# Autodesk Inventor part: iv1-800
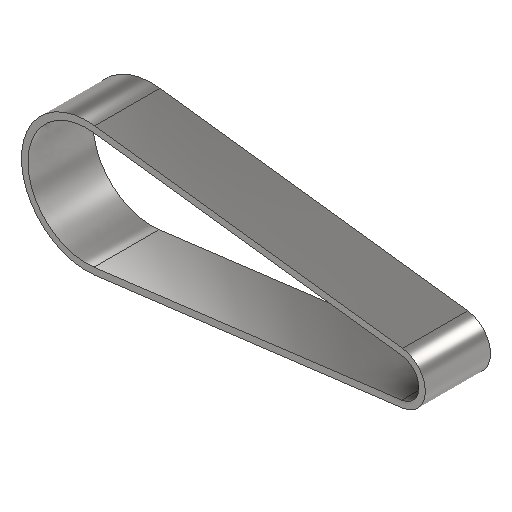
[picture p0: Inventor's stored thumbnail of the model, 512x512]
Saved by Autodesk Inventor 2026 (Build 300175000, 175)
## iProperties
Created: 2022-01
Part Number: iv1-800
Material: Steel, Mild
Document SubType Name: Modeling
Designer: Lars Bertram Pedersen
Density: 7.85 g/cm^3
Appearance: Semi-Polished
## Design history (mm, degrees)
sketch "Sketch1"
  geometry: L1 (3.125, 24.804)-(121.25, 9.922); L2 (3.125, -24.804)-(121.25, -9.922); A1 r 25 centre (0, 0) between (3.125, 24.804) and (3.125, -24.804); A2 r 10 centre (120, 0) between (121.25, -9.922) and (121.25, 9.922); 1 further point
  constraints: 4 end point, 4 point on circle, 4 tangent, 2 centre point, 1 coincident, 1 horizontal alignment
  dimensions: "d0" = 10 radius of A2; "d1" = 25 radius of A1; "d2" = 120 distance of A2.centre point (0, 0)
extrude "Extrusion1" new body sketch "Sketch1" distance "d3" = 25; taper "d4" = 0 deg
sketch "Sketch2"
  geometry: L1 (3.125, -24.804)-(121.25, -9.922) reference; L2 (121.25, 9.922)-(3.125, 24.804) reference; L3 (2.812, 22.324)-(120.938, 7.441); L4 (120.938, -7.441)-(2.813, -22.324); A1 r 10 centre (120, 0) between (121.25, -9.922) and (121.25, 9.922) reference; A2 r 25 centre (0, 0) between (3.125, 24.804) and (3.125, -24.804) reference; A3 r 7.5 centre (120, 0) between (120.938, -7.441) and (120.938, 7.441); A4 r 22.5 centre (0, 0) between (2.812, 22.324) and (2.813, -22.324); 1 further point
  constraints: 4 end point, 4 point on circle, 2 centre point, 3 other
  dimensions: "d5" = 2.5 distance between parallel lines of L3 L2
extrude "Extrusion2" cut sketch "Sketch2" extent not by distance; stored distance "d6" = 0; taper "d7" = 0 deg
body "Solid1"
node "Projected Loop1"
